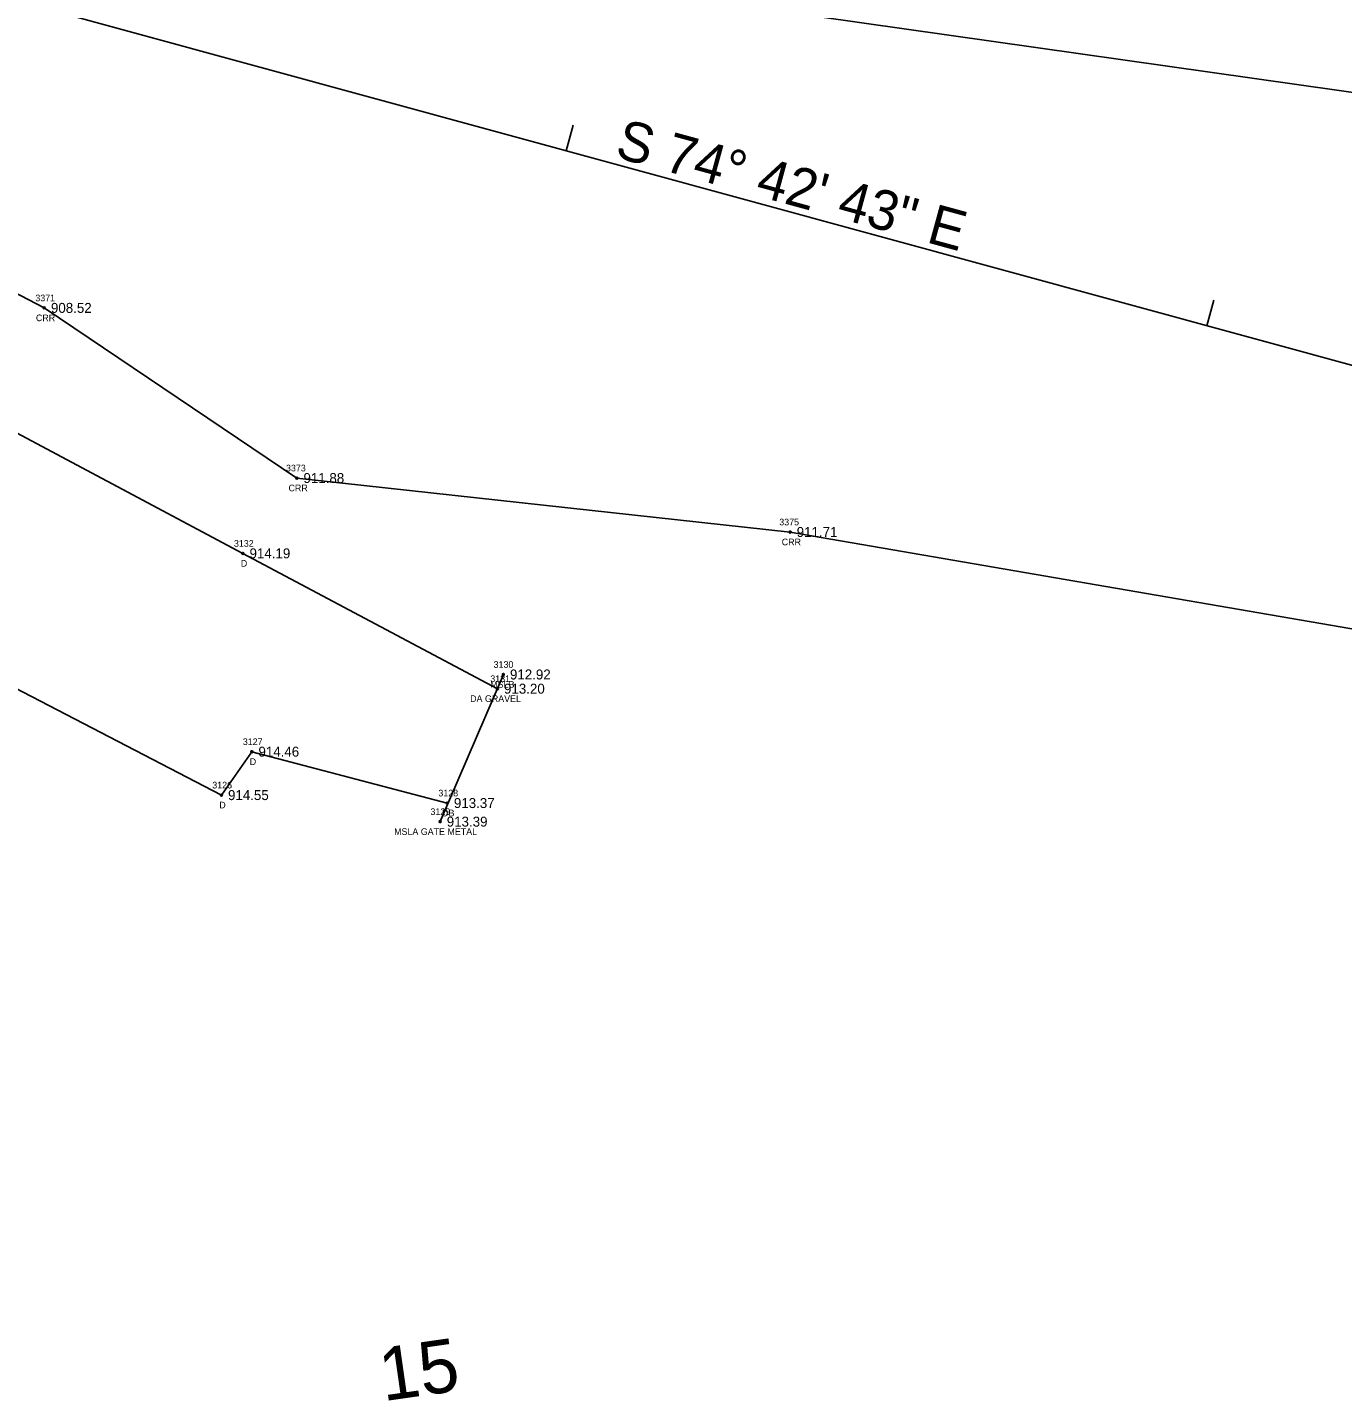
# Model space of a CAD drawing. Extents: x 1528109 to 1531398, y 1157799 to 1162548.
# Drawn here: x 1529775.9 to 1529973.9, y 1160034 to 1160240.8 of the extents above; entities that cross this region are included whole.
import ezdxf

# ---------------------------------------------------------------- set-up
doc = ezdxf.new("R2010")
doc.units = 0
for name, color, linetype in [('RD_EX_Driveway', 7, 'Continuous'), ('RD_EX_Driveway_txCode', 7, 'Continuous'), ('RD_EX_H2O', 7, 'Continuous'), ('RD_EX_H2O_txCode', 7, 'Continuous'), ('RD_EX_Misc', 7, 'Continuous'), ('RD_EX_Misc_txCode', 7, 'Continuous'), ('RD_EX_TX_Driveway_ELEV', 7, 'Continuous'), ('RD_EX_TX_H2O_ELEV', 7, 'Continuous'), ('RD_EX_TX_Misc_ELEV', 7, 'Continuous'), ('RD_HC_Cl', 7, 'Continuous'), ('RD_HC_Data', 7, 'Continuous'), ('RD_HC_Data_Tic', 7, 'Continuous'), ('RD_HC_TX_Sta50', 7, 'Continuous'), ('RD_SMD_Locator', 7, 'Continuous')]:
    doc.layers.add(name, color=color, linetype=linetype)

msp = doc.modelspace()

# ---------------------------------------------------------------- linework, layer by layer
at = {"layer": 'RD_EX_Driveway'}
for points in [[(1529846.69, 1160141.22), (1529808.38, 1160161.6), (1529767.49, 1160183.39), (1529741.09, 1160193.79), (1529707.45, 1160193.32), (1529684.65, 1160198.67)], [(1529711.85, 1160119.44), (1529726.2, 1160142.31), (1529749.24, 1160154.21), (1529805.14, 1160125.19), (1529809.72, 1160131.73), (1529839.15, 1160123.99)]]:
    msp.add_lwpolyline(points, dxfattribs=at)
at = {"layer": 'RD_EX_H2O'}
for points in [[(1529726.41, 1160311.29), (1529822.85, 1160258.09), (1529888.47, 1160243.37), (1529986.9, 1160229.42), (1530037.08, 1160228.61), (1530104.23, 1160168.21), (1530147.93, 1160110.54), (1530175.68, 1160088.08)], [(1529649.01, 1160227.21), (1529688.09, 1160231.48), (1529726.42, 1160225.69), (1529778.48, 1160198.58), (1529816.5, 1160172.95), (1529890.76, 1160164.82), (1530012.06, 1160143.92), (1530047.21, 1160111.79), (1530065, 1160080.23), (1530106.89, 1160040.72)]]:
    msp.add_lwpolyline(points, dxfattribs=at)
at = {"layer": 'RD_EX_Misc'}
msp.add_line((1529838.07, 1160121.19), (1529847.59, 1160143.36), dxfattribs=at)
at = {"layer": 'RD_HC_Cl'}
msp.add_line((1529753.92, 1160250.44), (1530030.68, 1160174.79), dxfattribs=at)
at = {"layer": 'RD_HC_Data_Tic'}
for p, q in [((1529857.05, 1160222.25), (1529858.1, 1160226.11)), ((1529953.51, 1160195.88), (1529954.56, 1160199.74))]:
    msp.add_line(p, q, dxfattribs=at)
at = {"layer": 'RD_SMD_Locator'}
for centre in [(1529778.48, 1160198.58), (1529816.5, 1160172.95), (1529890.76, 1160164.82), (1529808.38, 1160161.6), (1529847.59, 1160143.36), (1529846.69, 1160141.22), (1529809.72, 1160131.73), (1529805.14, 1160125.19), (1529839.15, 1160123.99), (1529838.07, 1160121.19)]:
    msp.add_circle(centre, 0.15, dxfattribs=at)

# ---------------------------------------------------------------- texts
at = {"layer": 'RD_EX_Driveway_txCode'}
for s, p in [('3132', (1529807.03, 1160162.6)), ('D', (1529808.07, 1160159.6)), ('3131', (1529845.63, 1160142.22)), ('DA GRAVEL', (1529842.59, 1160139.22)), ('3127', (1529808.37, 1160132.73)), ('D', (1529809.41, 1160129.73)), ('3126', (1529803.77, 1160126.19)), ('3128', (1529837.81, 1160124.99)), ('D', (1529804.83, 1160123.19)), ('DB', (1529838.37, 1160121.99))]:
    msp.add_text(s, height=1, dxfattribs=at).set_placement(p)
at = {"layer": 'RD_EX_H2O_txCode'}
for s, p in [('3371', (1529777.13, 1160199.58)), ('CRR', (1529777.22, 1160196.58)), ('3373', (1529814.87, 1160173.95)), ('CRR', (1529815.25, 1160170.95)), ('3375', (1529889.13, 1160165.82)), ('CRR', (1529889.51, 1160162.82))]:
    msp.add_text(s, height=1, dxfattribs=at).set_placement(p)
at = {"layer": 'RD_EX_Misc_txCode'}
for s, p in [('3130', (1529846.13, 1160144.36)), ('MSLB', (1529845.62, 1160141.36)), ('3129', (1529836.62, 1160122.19)), ('MSLA GATE METAL', (1529831.15, 1160119.19))]:
    msp.add_text(s, height=1, dxfattribs=at).set_placement(p)
at = {"layer": 'RD_EX_TX_Driveway_ELEV'}
for s, p in [('914.19', (1529809.38, 1160160.85)), ('913.20', (1529847.69, 1160140.47)), ('914.46', (1529810.72, 1160130.98)), ('914.55', (1529806.14, 1160124.44)), ('913.37', (1529840.15, 1160123.24))]:
    msp.add_text(s, height=1.5, dxfattribs=at).set_placement(p)
at = {"layer": 'RD_EX_TX_H2O_ELEV'}
for s, p in [('908.52', (1529779.48, 1160197.83)), ('911.88', (1529817.5, 1160172.2)), ('911.71', (1529891.76, 1160164.07))]:
    msp.add_text(s, height=1.5, dxfattribs=at).set_placement(p)
at = {"layer": 'RD_EX_TX_Misc_ELEV'}
for s, p in [('912.92', (1529848.59, 1160142.61)), ('913.39', (1529839.07, 1160120.44))]:
    msp.add_text(s, height=1.5, dxfattribs=at).set_placement(p)
at = {"layer": 'RD_HC_Data'}
msp.add_text('S 74%%d 42\' 43" E', height=6, rotation=344.7119, dxfattribs=at).set_placement((1529864.2, 1160221.33))
at = {"layer": 'RD_HC_TX_Sta50'}
msp.add_text('15', height=8, rotation=8.1288, dxfattribs=at).set_placement((1529829.54, 1160033.87))

doc.saveas('drawing.dxf')
